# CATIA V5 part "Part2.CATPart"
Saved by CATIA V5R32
Part number: Part2
Bounding box of the stored display mesh (mm): x -29.961 to 100, y -30 to 30, z -29.961 to 29.961
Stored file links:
  D:\PROJECTS\Project 2022\CATIA V5 6R 2022\Resources\Part Files\c16_catia_v5_6r2022_prt\Spherical Joint-(Fig16-27)\Part2.CATPart
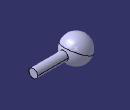
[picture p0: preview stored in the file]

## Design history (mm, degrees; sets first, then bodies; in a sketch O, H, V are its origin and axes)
Body1 (main body)
  Sketch1 on xy-plane, origin (0, 0, 0), H (1, 0, 0), V (0, 1, 0)
    arc A1 centre (0, 0) radius 30 from (0, -30) to (0, 30) ccw
    point P1 (0, 30)
    point P2 (0, -30)
    line L1 (0, -30) -> (0, 30)
    length L1 = 60
    coincidence: P1 V, P2 V
    vertical: L1 V
  Shaft1: profile Sketch1, axis Sketch1.L1, angle 360
  Sketch2 on yz-plane, origin (0, 0, 0), H (0, 1, 0), V (0, 0, 1)
    circle A1 centre (0, 0) radius 10
    radius A1 = 10
  Pad1: profile Sketch2, direction (1, 0, 0), length 100
  Point1: (0, 0, 0)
